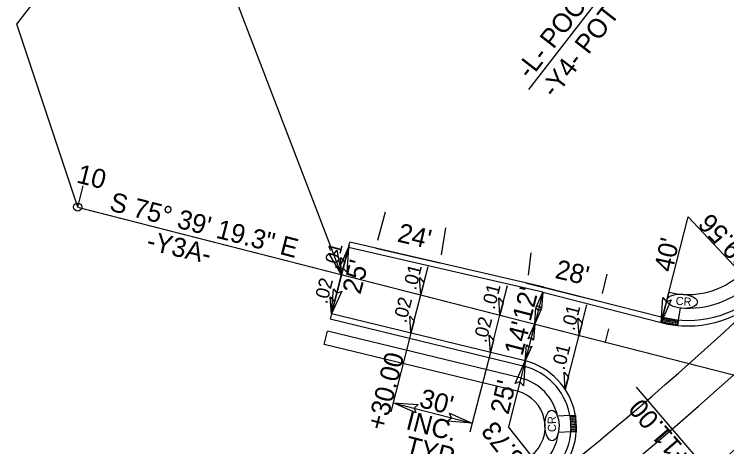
# Model space of a CAD drawing. Extents: x 2010838 to 2015151, y 441905 to 447792.
# Drawn here: x 2013816.3 to 2014077.9, y 445241.4 to 445400.2 of the extents above; entities that cross this region are included whole.
import ezdxf

# ---------------------------------------------------------------- set-up
doc = ezdxf.new("R2010")
doc.units = 0
for name, color, linetype in [('A-Wall-Blow', 7, 'Continuous'), ('A-Wall-Comp', 7, 'Continuous'), ('B-Border', 7, 'Continuous'), ('C-Building', 7, 'Continuous'), ('C-EOP 1', 7, 'Continuous'), ('C-Grave Plots', 7, 'Continuous'), ('CLRD', 7, 'Continuous'), ('Cont-2-Lidar', 7, 'Continuous'), ('Default_10ft_LIDAR_Contou', 7, 'Continuous'), ('Default_2FT_LIDAR_Contour', 7, 'Continuous'), ('HATCH', 7, 'Continuous'), ('s-Existing Major', 7, 'Continuous'), ('S-Existing Minor', 7, 'Continuous'), ('S-overhead electric', 7, 'Continuous'), ('TEXT-LG', 7, 'Continuous'), ('TEXT-MED', 7, 'Continuous'), ('X2', 7, 'Continuous'), ('X4', 7, 'Continuous')]:
    doc.layers.add(name, color=color, linetype=linetype)

msp = doc.modelspace()

# ---------------------------------------------------------------- linework, layer by layer
at = {"layer": 'A-Wall-Blow'}
for p, q in [((2013936.5, 445304.58), (2013939.06, 445314.59)), ((2013965.57, 445297.15), (2013968.23, 445307.57)), ((2013932.81, 445290.14), (2013936.5, 445304.58)), ((2013994.63, 445289.72), (2013997.4, 445300.54)), ((2013961.97, 445283.07), (2013965.57, 445297.15)), ((2014023.7, 445282.29), (2014026.57, 445293.52)), ((2013991.12, 445276), (2013994.63, 445289.72)), ((2014018.61, 445262.41), (2014023.7, 445282.29))]:
    msp.add_line(p, q, dxfattribs=at)
at = {"layer": 'A-Wall-Comp'}
for points in [[(2013936.5, 445304.58), (2013936.05, 445310.89), (2013937.65, 445309.07)], [(2013965.57, 445297.15), (2013965.12, 445303.46), (2013966.71, 445301.63)], [(2013932.81, 445290.14), (2013932.36, 445296.45), (2013933.95, 445294.62)], [(2013994.63, 445289.72), (2013994.18, 445296.03), (2013995.78, 445294.2)], [(2013961.97, 445283.07), (2013961.51, 445289.38), (2013963.11, 445287.55)], [(2014023.7, 445282.29), (2014023.24, 445288.59), (2014024.84, 445286.77)], [(2013991.12, 445276), (2013990.67, 445282.31), (2013992.27, 445280.48)], [(2014018.61, 445262.41), (2014018.16, 445268.72), (2014019.76, 445266.89)]]:
    msp.add_lwpolyline(points, close=True, dxfattribs=at)
at = {"layer": 'B-Border'}
msp.add_arc((2013223.9, 446217.91), 1265.25, 308.60336, 313.26766, dxfattribs=at)
at = {"layer": 'C-Building'}
for p, q in [((2013936.5, 445304.58), (2013937.74, 445309.43)), ((2014033.38, 445279.81), (2014034.62, 445284.65))]:
    msp.add_line(p, q, dxfattribs=at)
at = {"layer": 'C-EOP 1'}
msp.add_line((2013839.62, 445329.36), (2013841.6, 445337.11), dxfattribs=at)
at = {"layer": 'CLRD'}
for p in [(2013839.62, 445329.36), (2013841.07, 445328.99)]:
    msp.add_line(p, (2014104.53, 445261.61), dxfattribs=at)
msp.add_arc((2013223.9, 446217.91), 1300, 266.62643, 322.2051, dxfattribs=at)
at = {"layer": 'Default_10ft_LIDAR_Contou'}
for p, q in [((2013817.29, 445396.57), (2013893.45, 445494.77)), ((2014081.56, 445471.13), (2014005.12, 445372.57)), ((2013839.62, 445329.36), (2013817.29, 445396.57))]:
    msp.add_line(p, q, dxfattribs=at)
msp.add_circle((2013839.62, 445329.36), 1.5, dxfattribs=at)
at = {"layer": 'HATCH'}
for radius, start, end in [(1279.25, 293.04012, 322.2051), (1308.75, 309.42938, 312.84627), (1320.75, 278.35841, 312.84627)]:
    msp.add_arc((2013223.9, 446217.91), radius, start, end, dxfattribs=at)
at = {"layer": 's-Existing Major'}
for points in [[(2013934.73, 445313.54), (2013936.5, 445304.58), (2013931.77, 445312.46), (2013933.67, 445311.96)], [(2013935.33, 445306.25), (2013939.06, 445314.59), (2013938.37, 445305.42), (2013937.1, 445306.93)], [(2013936.54, 445298.48), (2013932.81, 445290.14), (2013933.5, 445299.31), (2013934.77, 445297.8)], [(2014007.94, 445292.66), (2014010.36, 445298.08), (2014009.91, 445292.13), (2014009.09, 445293.11)], [(2014057.52, 445295.31), (2014053.79, 445286.98), (2014054.48, 445296.14), (2014055.75, 445294.63)], [(2014009.82, 445291.87), (2014007.39, 445286.46), (2014007.84, 445292.41), (2014008.66, 445291.43)], [(2014004.96, 445281.04), (2014007.39, 445286.46), (2014006.94, 445280.5), (2014006.12, 445281.48)], [(2014006.35, 445278.31), (2014003.92, 445272.89), (2014004.37, 445278.85), (2014005.19, 445277.87)], [(2014000.19, 445264.56), (2014003.92, 445272.89), (2014003.23, 445263.73), (2014001.96, 445265.24)], [(2013963.79, 445253.82), (2013955.42, 445257.46), (2013964.59, 445256.87), (2013963.09, 445255.59)], [(2013976.15, 445253.76), (2013984.48, 445250.03), (2013975.32, 445250.72), (2013976.83, 445251.99)]]:
    msp.add_lwpolyline(points, close=True, dxfattribs=at)
at = {"layer": 'S-Existing Minor'}
for p, q in [((2013936.5, 445304.58), (2013881.87, 445447.14)), ((2014053.79, 445286.98), (2014063.7, 445325.73)), ((2014091.12, 445296.6), (2014063.7, 445325.73)), ((2013939.25, 445315.33), (2013932.81, 445290.14)), ((2014010.36, 445298.08), (2014007.39, 445286.46)), ((2014007.39, 445286.46), (2014003.92, 445272.89)), ((2013961.97, 445283.07), (2013954.57, 445254.16)), ((2013991.12, 445276), (2013983.64, 445246.72)), ((2014003.92, 445272.89), (2013997.73, 445248.67)), ((2014044.68, 445263.22), (2014066.48, 445237.86)), ((2013955.42, 445257.46), (2013984.48, 445250.03)), ((2014013.33, 445229.14), (2013997.73, 445248.67))]:
    msp.add_line(p, q, dxfattribs=at)
at = {"layer": 'S-overhead electric'}
for p, q in [((2013949.77, 445317.24), (2013952.58, 445327.63)), ((2013973.15, 445311.83), (2013974.78, 445321.81)), ((2014010.36, 445298.08), (2013939.06, 445314.59)), ((2014005.16, 445304.37), (2014006.12, 445312.58)), ((2014032.33, 445297.61), (2014033.98, 445304.71)), ((2014010.36, 445298.08), (2014053.79, 445286.98)), ((2014003.92, 445272.89), (2013932.81, 445290.14))]:
    msp.add_line(p, q, dxfattribs=at)
for centre, radius, start, end in [((2014063.7, 445325.73), 40, 255.6554, 313.2677), ((2013997.73, 445248.67), 25, 308.6034, 75.6554)]:
    msp.add_arc(centre, radius, start, end, dxfattribs=at)
at = {"layer": 'TEXT-LG'}
for p, q in [((2014056.64, 445298.12), (2014054.28, 445288.91)), ((2014060.2, 445287.89), (2014060.96, 445292.34)), ((2014053.94, 445286.94), (2014054.28, 445288.91)), ((2014054.28, 445288.91), (2014060.2, 445287.89)), ((2014060.2, 445287.89), (2014059.86, 445285.92)), ((2014053.94, 445286.94), (2014059.86, 445285.92)), ((2013930.1, 445278.97), (2013931.28, 445283.82)), ((2014002.09, 445266.65), (2013931.28, 445283.82)), ((2014000.91, 445261.79), (2013930.1, 445278.97)), ((2014020.42, 445252.81), (2014015.81, 445252.58)), ((2014020.37, 445252.8), (2014022.37, 445252.9)), ((2014020.37, 445252.8), (2014020.67, 445246.81)), ((2014022.37, 445252.9), (2014022.67, 445246.91)), ((2014020.71, 445246.81), (2014016.11, 445246.58)), ((2014022.67, 445246.91), (2014020.67, 445246.81))]:
    msp.add_line(p, q, dxfattribs=at)
for centre in [(2014054.46, 445287.68), (2014054.54, 445288.13), (2014054.6, 445288.56), (2014055.02, 445287.58), (2014055.11, 445288.03), (2014055.17, 445288.46), (2014055.61, 445287.48), (2014055.7, 445287.93), (2014055.76, 445288.35), (2014056.18, 445287.38), (2014056.26, 445287.83), (2014056.33, 445288.25), (2014056.77, 445287.27), (2014056.85, 445287.73), (2014056.92, 445288.15), (2014057.37, 445287.17), (2014057.45, 445287.62), (2014057.52, 445288.05), (2014058.04, 445287.52), (2014058.11, 445287.95), (2014058.61, 445287.42), (2014058.67, 445287.85), (2014059.2, 445287.32), (2014059.26, 445287.74), (2014059.77, 445287.22), (2014059.83, 445287.64), (2014054.37, 445287.13), (2014054.94, 445287.03), (2014055.53, 445286.93), (2014056.09, 445286.83), (2014056.68, 445286.73), (2014057.28, 445286.63), (2014057.87, 445286.52), (2014057.96, 445287.07), (2014058.44, 445286.42), (2014058.53, 445286.97), (2014059.03, 445286.32), (2014059.12, 445286.87), (2014059.6, 445286.22), (2014059.68, 445286.77), (2014020.65, 445252.43), (2014020.67, 445251.86), (2014020.7, 445251.26), (2014020.73, 445250.68), (2014021.2, 445252.47), (2014021.23, 445251.89), (2014021.25, 445251.29), (2014021.28, 445250.72), (2014021.66, 445252.48), (2014021.69, 445251.91), (2014021.71, 445251.31), (2014021.74, 445250.74), (2014022.09, 445252.51), (2014022.11, 445251.94), (2014022.14, 445251.34), (2014022.17, 445250.77), (2014020.76, 445250.08), (2014020.79, 445249.48), (2014020.82, 445248.88), (2014020.84, 445248.3), (2014021.31, 445250.12), (2014021.34, 445249.51), (2014021.37, 445248.91), (2014021.4, 445248.34), (2014021.77, 445250.14), (2014021.8, 445249.53), (2014021.83, 445248.93), (2014021.86, 445248.36), (2014022.2, 445250.17), (2014022.23, 445249.56), (2014022.26, 445248.96), (2014022.29, 445248.39), (2014020.87, 445247.7), (2014020.9, 445247.13), (2014021.43, 445247.74), (2014021.45, 445247.17), (2014021.89, 445247.76), (2014021.91, 445247.18), (2014022.31, 445247.79), (2014022.34, 445247.22)]:
    msp.add_circle(centre, 0.0869, dxfattribs=at)
for centre, radius, start, end in [((2014063.7, 445325.73), 28.5, 255.6554, 313.2677), ((2014063.7, 445325.73), 33.5, 265.3172, 313.2677), ((2013997.73, 445248.67), 18.5, 12.1845, 75.6554), ((2013997.73, 445248.67), 13.5, 308.6034, 75.6554), ((2013997.73, 445248.67), 18.5, 308.6034, 353.5212)]:
    msp.add_arc(centre, radius, start, end, dxfattribs=at)
at = {"layer": 'TEXT-MED'}
for p, q in [((2013939.06, 445314.59), (2013939.55, 445316.52)), ((2014010.81, 445300.03), (2013939.51, 445316.53)), ((2014010.86, 445300.02), (2014054.28, 445288.91)), ((2013932.81, 445290.14), (2013932.34, 445288.2)), ((2014003.15, 445271.02), (2013932.34, 445288.2))]:
    msp.add_line(p, q, dxfattribs=at)
for centre, radius, start, end in [((2014063.7, 445325.73), 38, 255.6554, 313.2677), ((2013997.73, 445248.67), 23, 308.6034, 75.6554)]:
    msp.add_arc(centre, radius, start, end, dxfattribs=at)
at = {"layer": 'X2'}
for p, q in [((2013949.09, 445314.32), (2013972.47, 445308.91)), ((2014004.43, 445301.46), (2014031.61, 445294.69))]:
    msp.add_line(p, q, dxfattribs=at)
at = {"layer": 'X4'}
for centre, major_axis in [((2014061.54, 445294.8), (5.59, -0.45)), ((2014013.73, 445249.16), (-0.1, 5.61))]:
    msp.add_ellipse(centre, major_axis=major_axis, ratio=0.462467, dxfattribs=at)

# ---------------------------------------------------------------- texts
at = {"layer": 'A-Wall-Blow'}
for s, p in [('.01', (2013934.68, 445306.39)), ('.01', (2013963.77, 445298.61)), ('.02', (2013931.14, 445293.59)), ('.01', (2013992.65, 445291.51)), ('.02', (2013960.17, 445286.57)), ('.01', (2014021.9, 445283.74)), ('.02', (2013989.58, 445279.33)), ('.01', (2014018.3, 445269.29))]:
    msp.add_text(s, height=5, rotation=75.6554, dxfattribs=at).set_placement(p)
at = {"layer": 'C-Grave Plots'}
for s, rotation, p in [('+69.56', 133.2683, (2014091.76, 445306.57)), ("24'", 346.7799, (2013956.62, 445316.77)), ("40'", 77.5921, (2014057.97, 445305.2)), ("25'", 75.6531, (2013943.41, 445297.07)), ("28'", 346.7799, (2014014.53, 445303.4)), ("12'", 75.6531, (2014005.86, 445287.09)), ("14'", 75.6531, (2014002.85, 445274.47)), ('+30.00', 75.6507, (2013952.42, 445246.96)), ("25'", 76.4848, (2013997.74, 445252.91)), ("30'", 345.5608, (2013964.66, 445256.06)), ('INC. ', 345.5608, (2013959.74, 445247.93)), ('+63.73', 128.6951, (2014010.82, 445228.8)), ('TYP', 345.5608, (2013959.31, 445238.65))]:
    msp.add_text(s, height=7, rotation=rotation, dxfattribs=at).set_placement(p)
at = {"layer": 'Cont-2-Lidar'}
for s, rotation, p in [('S 75%%d 39\' 19.3" E', 345.6554, (2013850.92, 445328.19)), ('-Y3A-', 346.8406, (2013864.47, 445313.91))]:
    msp.add_text(s, height=7, rotation=rotation, dxfattribs=at).set_placement(p)
at = {"layer": 'Default_10ft_LIDAR_Contou'}
for s, p in [('-L- POC Sta. 40+80.44=', (2014005.65, 445376.01)), ('-Y4- POT Sta.  10+00.00', (2014014.64, 445369.04))]:
    msp.add_text(s, height=7, rotation=52.2051, dxfattribs=at).set_placement(p)
at = {"layer": 'Default_2FT_LIDAR_Contour'}
msp.add_text('10', height=7, rotation=345.6554, dxfattribs=at).set_placement((2013838.88, 445338.45))
at = {"layer": 'S-Existing Minor'}
msp.add_text('+11.00', height=7, rotation=130.6867, dxfattribs=at).set_placement((2014065.49, 445237.72))
at = {"layer": 'X4'}
for rotation, p in [(355.4021, (2014059.07, 445293.51)), (91.0423, (2014015.25, 445246.84))]:
    msp.add_text('CR', height=3, rotation=rotation, dxfattribs=at).set_placement(p)

doc.saveas('drawing.dxf')
